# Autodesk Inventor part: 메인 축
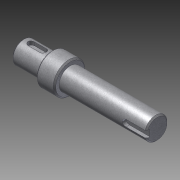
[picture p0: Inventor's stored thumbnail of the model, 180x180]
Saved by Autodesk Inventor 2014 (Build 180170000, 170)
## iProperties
Created: 2016-04
Part Number: 메인 축
Document SubType Name: Modeling
Designer: mdu
Density: 7.86 g/cm^3
Mass: 230.24 g
Surface Area: 74.3518 cm^2
Volume: 29.2926 cm^3
Material: 강철, 연강
Appearance: 반광택
Author: mdu
Revision Number: 1
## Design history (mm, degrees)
sketch "스케치1"
  geometry: L1 (10.497, -57.5)-(112.497, -57.5); L2 (10.497, -66)-(32.497, -66); L3 (32.497, -69.5)-(46.5, -69.5); L4 (46.5, -66)-(112.497, -66); L5 (112.497, -66)-(112.497, -57.5); L6 (10.497, -66)-(10.497, -57.5); L7 (46.5, -69.749)-(46.5, -45.251) reference; L8 (46.5, -69.5)-(46.5, -66); L9 (32.497, -69.5)-(32.497, -66); L10 (32.497, -35)-(32.497, -80) reference; 3 further points
  constraints: 16 end point, 3 point on line, 2 parallel, 2 perpendicular, 1 collinear, 1 horizontal, 1 midpoint
  dimensions: "d0" = 17 diameter of L4 L1; "d1" = 24 diameter of L3 L1; "d2" = 22 distance of L2.start L2.end; "d3" = 65.99692 distance of L4.start L4.end (derived); "d5" = 17 diameter of L2 L1; "d19" = 80 distance between parallel lines of L5 L9
revolve "회전1" sketch "스케치1" stored, may be unused: angle "d4" = 90 deg
feature "면 이동1"
chamfer "모따기1" distance "d6" = 0.5; stored, may be unused: second distance "d7" = 2, angle "d8" = 45 deg
node "작업 평면1"
sketch "스케치2"
  geometry: L1 (-11, -8)-(-11, 8) reference; L2 (-4.5, 2.5)-(4.5, 2.5); L3 (4.5, -2.5)-(-4.5, -2.5); A1 r 2.5 centre (4.5, 0) between (4.5, -2.5) and (4.5, 2.5); A2 r 2.5 centre (-4.5, 0) between (-4.5, 2.5) and (-4.5, -2.5); 2 further points
  constraints: 4 end point, 4 point on circle, 4 tangent, 2 centre point, 1 horizontal alignment, 1 midpoint, 1 parallel, 1 perpendicular
  dimensions: "d9" = 5 distance between parallel lines of L3 L2; "d10" = 14 dimension on A1 A2; "d11" = 4 distance edge to line of A2 L1
extrude "돌출1" cut sketch "스케치2" distance "d12" = 3; taper "d13" = 0 deg
node "작업 평면2"
sketch "스케치3"
  geometry: L1 (32.998, 8)-(32.998, -8) reference; L2 (32.998, 2.5)-(17.498, 2.5); L3 (17.498, -2.5)-(32.998, -2.5); A1 r 2.5 centre (17.498, 0) between (17.498, 2.5) and (17.498, -2.5); 2 further points
  constraints: 4 end point, 2 perpendicular, 2 point on circle, 2 point on line, 2 tangent, 1 centre point, 1 horizontal alignment, 1 midpoint
  dimensions: "d14" = 5 distance between parallel lines of L3 L2; "d15" = 18 dimension on A1 L1
extrude "돌출2" cut sketch "스케치3" distance "d16" = 3; taper "d17" = 0 deg
node "솔리드1"
node "참조4"
node "참조5"
